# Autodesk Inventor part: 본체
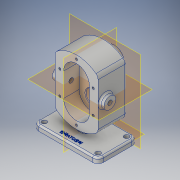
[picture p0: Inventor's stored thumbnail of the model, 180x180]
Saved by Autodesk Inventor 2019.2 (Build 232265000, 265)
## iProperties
Created: 2019-03
Part Number: 본체
Material: 알루미늄 6061
Document SubType Name: Modeling
Designer: User
Density: 2.7 g/cm^3
Appearance: 알루미늄 - 평지
Mass: 1185.36 g
Surface Area: 720.534 cm^2
Volume: 439.024 cm^3
Author: User
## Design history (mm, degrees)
sketch "스케치1"
  geometry: L1 (0, 84)-(0, -84) reference; L2 (-56, 0)-(56, 0) reference; L3 (-40, 44.721)-(-40, -44.721); L4 (40, -44.721)-(40, 44.721); A1 r 60 centre (0, 0) between (-40, -44.721) and (40, -44.721); A2 r 60 centre (0, 0) between (40, 44.721) and (-40, 44.721); 1 further point
  constraints: 4 end point, 4 point on circle, 2 centre point, 2 vertical, 1 coincident
  dimensions: "d1" = 80 distance between parallel lines of L4 L3; "d2" = 40 distance between parallel lines of L4 L1; "d3" = 60 radius of A2; "d4" = 60 radius of A1
extrude "돌출1" new body sketch "스케치1" distance "d5" = 53; taper "d6" = 0 deg
sketch "스케치2"
  geometry: L1 (0, 84)-(0, -84) reference; C1 r 19 at (0, 22); 1 further point
  constraints: 1 centre point, 1 point on line
  dimensions: "d7" = 38 diameter of C1; "d8" = 22 distance of point (0, 0) C1.centre
extrude "돌출2" join sketch "스케치2" distance "d9" = 70; taper "d10" = 0 deg
sketch "스케치3"
  geometry: L1 (44.721, 53)-(-44.721, 53) reference; L2 (0, 67)-(0, -31) reference; C1 r 11 at (0, 39); 1 further point
  constraints: 1 centre point, 1 point on line
  dimensions: "d11" = 22 diameter of C1; "d12" = 14 distance from line of L1 C1.centre
extrude "돌출3" join sketch "스케치3" stored distance "d13" = 96; taper "d14" = 0 deg
node "작업 평면1"
sketch "스케치4"
  geometry: L1 (60, 0)-(-60, 0); L2 (-60, 0)-(-60, 73); L3 (-60, 73)-(60, 73); L4 (60, 73)-(60, 0); L5 (0, -35)-(0, 91) reference; L6 (-84, 0)-(84, 0) reference; 1 further point
  constraints: 8 end point, 2 parallel, 1 collinear, 1 horizontal, 1 perpendicular
  dimensions: "d16" = 73 distance of L3.end L1.start; "d17" = 120 distance of L2.end L3.end; "d18" = 60 distance between parallel lines of L5 L4
extrude "돌출4" join sketch "스케치4" distance "d19" = 10; taper "d20" = 0 deg
sketch "스케치5"
  geometry: L1 (-45.169, 43)-(-68, 43); L2 (-68, 43)-(-68, 0); L3 (-68, 0)-(-45.169, 0); L4 (-45.169, 0)-(-45.169, 43); L5 (-68, 0)-(-68, 73) reference; L6 (-78, 0)-(-68, 0) reference; 1 further point
  constraints: 8 end point, 2 collinear, 2 parallel, 1 horizontal, 1 perpendicular
  dimensions: "d21" = 43 distance of L1.end L2.end; "d22" = 22.83133 distance of L1.start L1.end
extrude "돌출5" join sketch "스케치5" stored distance "d23" = 12; taper "d24" = 0 deg
sketch "스케치6"
  geometry: L1 (0, -22)-(0, 22); L2 (24, -22)-(24, 22); L3 (-24, 22)-(-24, -22); L4 (-84, 0)-(84, 0) reference; L5 (0, -105.6)-(0, 87.6) reference; A1 r 24 centre (0, -22) between (-24, -22) and (24, -22); A2 r 24 centre (0, 22) between (24, 22) and (-24, 22); 2 further points
  constraints: 8 end point, 4 point on circle, 4 tangent, 2 centre point, 1 collinear, 1 midpoint, 1 parallel, 1 vertical, 1 other
  dimensions: "d25" = 24 radius of A2; "d26" = 44 distance of L2.start L2.end
extrude "돌출6" cut sketch "스케치6" distance "d27" = 29; taper "d28" = 0 deg
sketch "스케치7"
  geometry: A1 r 24 centre (0, 22) between (24, 22) and (-24, 22) reference; 2 further points
  constraints: 1 coincident
hole "구멍1" sketch "스케치7" at (0, 22) diameter "d29" = 17; stored, may be unused: countersink angle "d33" = 90 deg, drill point angle "d35" = 118 deg; dims "d30" = 9, "d31" = 25, "d32" = 15, "d34" = 50
sketch "스케치8"
  geometry: A1 r 24 centre (0, -22) between (-24, -22) and (24, -22) reference; 2 further points
  constraints: 1 coincident
hole "구멍2" sketch "스케치8" at (0, -22) diameter "d36" = 25; stored, may be unused: countersink angle "d40" = 90 deg, drill point angle "d42" = 0 deg; dims "d37" = 9, "d38" = 25, "d39" = 17, "d41" = 15
sketch "스케치9"
  geometry: C1 r 19 at (0, 0) reference; 2 further points
  constraints: 1 coincident
hole "구멍3" sketch "스케치9" at (0, 0) diameter "d43" = 28; stored, may be unused: countersink angle "d47" = 90 deg, drill point angle "d49" = 0 deg; dims "d44" = 9, "d45" = 25, "d46" = 17, "d48" = 7.3
sketch "스케치10"
  geometry: C1 r 11 at (0, 0) reference; 2 further points
  constraints: 1 coincident
hole "구멍4" sketch "스케치10" at (0, 0) diameter "d50" = 8.376; stored, may be unused: countersink angle "d54" = 90 deg, drill point angle "d56" = 0 deg; dims "d51" = 50, "d52" = 25, "d53" = 17, "d55" = 50
sketch "스케치11"
  geometry: C1 r 11 at (0, 0) reference; 2 further points
  constraints: 1 coincident
hole "구멍5" sketch "스케치11" at (0, 0) diameter "d57" = 8.376; stored, may be unused: countersink angle "d61" = 90 deg, drill point angle "d63" = 0 deg; dims "d58" = 50, "d59" = 25, "d60" = 17, "d62" = 50
sketch "스케치12"
  geometry: L1 (-24, -22)-(-24, 22) reference; L2 (24, 22)-(24, -22) reference; L3 (-31, 22)-(-31, -22); L4 (31, -22)-(31, 22); A1 r 24 centre (0, 22) between (24, 22) and (-24, 22) reference; A2 r 24 centre (0, -22) between (-24, -22) and (24, -22) reference; A3 r 31 centre (0, -22) between (-31, -22) and (31, -22); A4 r 31 centre (0, 22) between (31, 22) and (-31, 22); 1 further point
  constraints: 4 end point, 4 point on circle, 2 centre point, 3 other
  dimensions: "d64" = 7 radial gap between concentric circles of A1 A4
hole "구멍6" sketch "스케치12" at (-31, -22), (-31, 22), (31, 22), (31, -22) diameter "d65" = 4.134; stored, may be unused: countersink angle "d69" = 90 deg, drill point angle "d71" = 118 deg; dims "d66" = 10, "d67" = 25, "d68" = 17, "d70" = 12
sketch "스케치13"
  geometry: L1 (0, 0)-(0, 53)
  constraints: 2 end point, 1 vertical
  dimensions: "d72" = 53 distance of L1.start L1.end
hole "구멍7" sketch "스케치13" at (0, 53) diameter "d73" = 4.134; stored, may be unused: countersink angle "d77" = 90 deg, drill point angle "d79" = 118 deg; dims "d74" = 10, "d75" = 25, "d76" = 17, "d78" = 12
chamfer "모따기1" distance "d80" = 1; stored, may be unused: second distance "d81" = 2, angle "d82" = 45 deg
fillet "모깎기1" dims "d83" = 10
sketch "스케치14"
  geometry: A1 r 10 centre (-50, -63) between (-60, -63) and (-50, -73) reference; A2 r 10 centre (-50, -10) between (-50, 0) and (-60, -10) reference; A3 r 10 centre (50, -63) between (50, -73) and (60, -63) reference; A4 r 10 centre (50, -10) between (60, -10) and (50, 0) reference; 5 further points
  constraints: 4 coincident
hole "구멍8" sketch "스케치14" at (-50, -63), (-50, -10), (50, -63), (50, -10) diameter "d84" = 9; stored, may be unused: countersink angle "d88" = 90 deg, drill point angle "d90" = 118 deg; dims "d85" = 10, "d86" = 25, "d87" = 17, "d89" = 12
fillet "모깎기3" dims "d92" = 10
fillet "모깎기4" dims "d93" = 3
fillet "모깎기5" dims "d94" = 3
fillet "모깎기6" dims "d95" = 3
fillet "모깎기7" dims "d96" = 3
fillet "모깎기8" dims "d97" = 0.5
chamfer "모따기2" distance "d98" = 0.7; stored, may be unused: second distance "d99" = 2, angle "d100" = 30 deg
sketch "스케치15"
  geometry: L1 (-60, -10)-(-60, -63) reference; L2 (-50, -73)-(50, -73) reference; 2 further points
  constraints: 1 other
  dimensions: "d101" = 60 distance from line of L1 point (0, -63); "d102" = 10 distance from line of L2 point (0, -63)
feature "엠보싱1" sketch "스케치15" dims "d0" = 120, "d103" = 0.5, "d104" = 0
fillet "모깎기9" dims "d105" = 3
node "솔리드1"
mirror "미러1"
other parameters: "d15" = -78
